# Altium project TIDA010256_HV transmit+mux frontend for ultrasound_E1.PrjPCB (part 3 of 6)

## Sheet 14_XDS110_Debugger.SchDoc
size 431 x 279 mm; Date: Not shown in title block; ApprovedBy: Not shown in title block; CheckedBy: Not shown in title block; Author: Not shown in title block; CompanyName: Not shown in title block; Engineer: Not shown in title block; Organization: Not shown in title block; Address1: Not shown in title block; Address2: Not shown in title block; Address3: Not shown in title block; Address4: Not shown in title block; DocumentNumber: 6; Revision: Use project parameter SCH_Rev; SheetNumber: 6; SheetTotal: 18; PageSetup: Record=PageOptions¦CenterHorizontal=True¦CenterVertical=True¦PrintScale=1.00¦XCorrection=1.00¦YCorrection=1.00¦PrintKind=0¦BorderSize=5000000¦LeftOffset=0¦BottomOffset=0¦Orientation=2¦PaperLength=1000¦PaperWidth=1000¦Scale=100¦PaperSource=15¦PrintQuality=600¦MediaType=1¦DitherType=10¦PaperKind=Letter¦PrintScaleMode=1
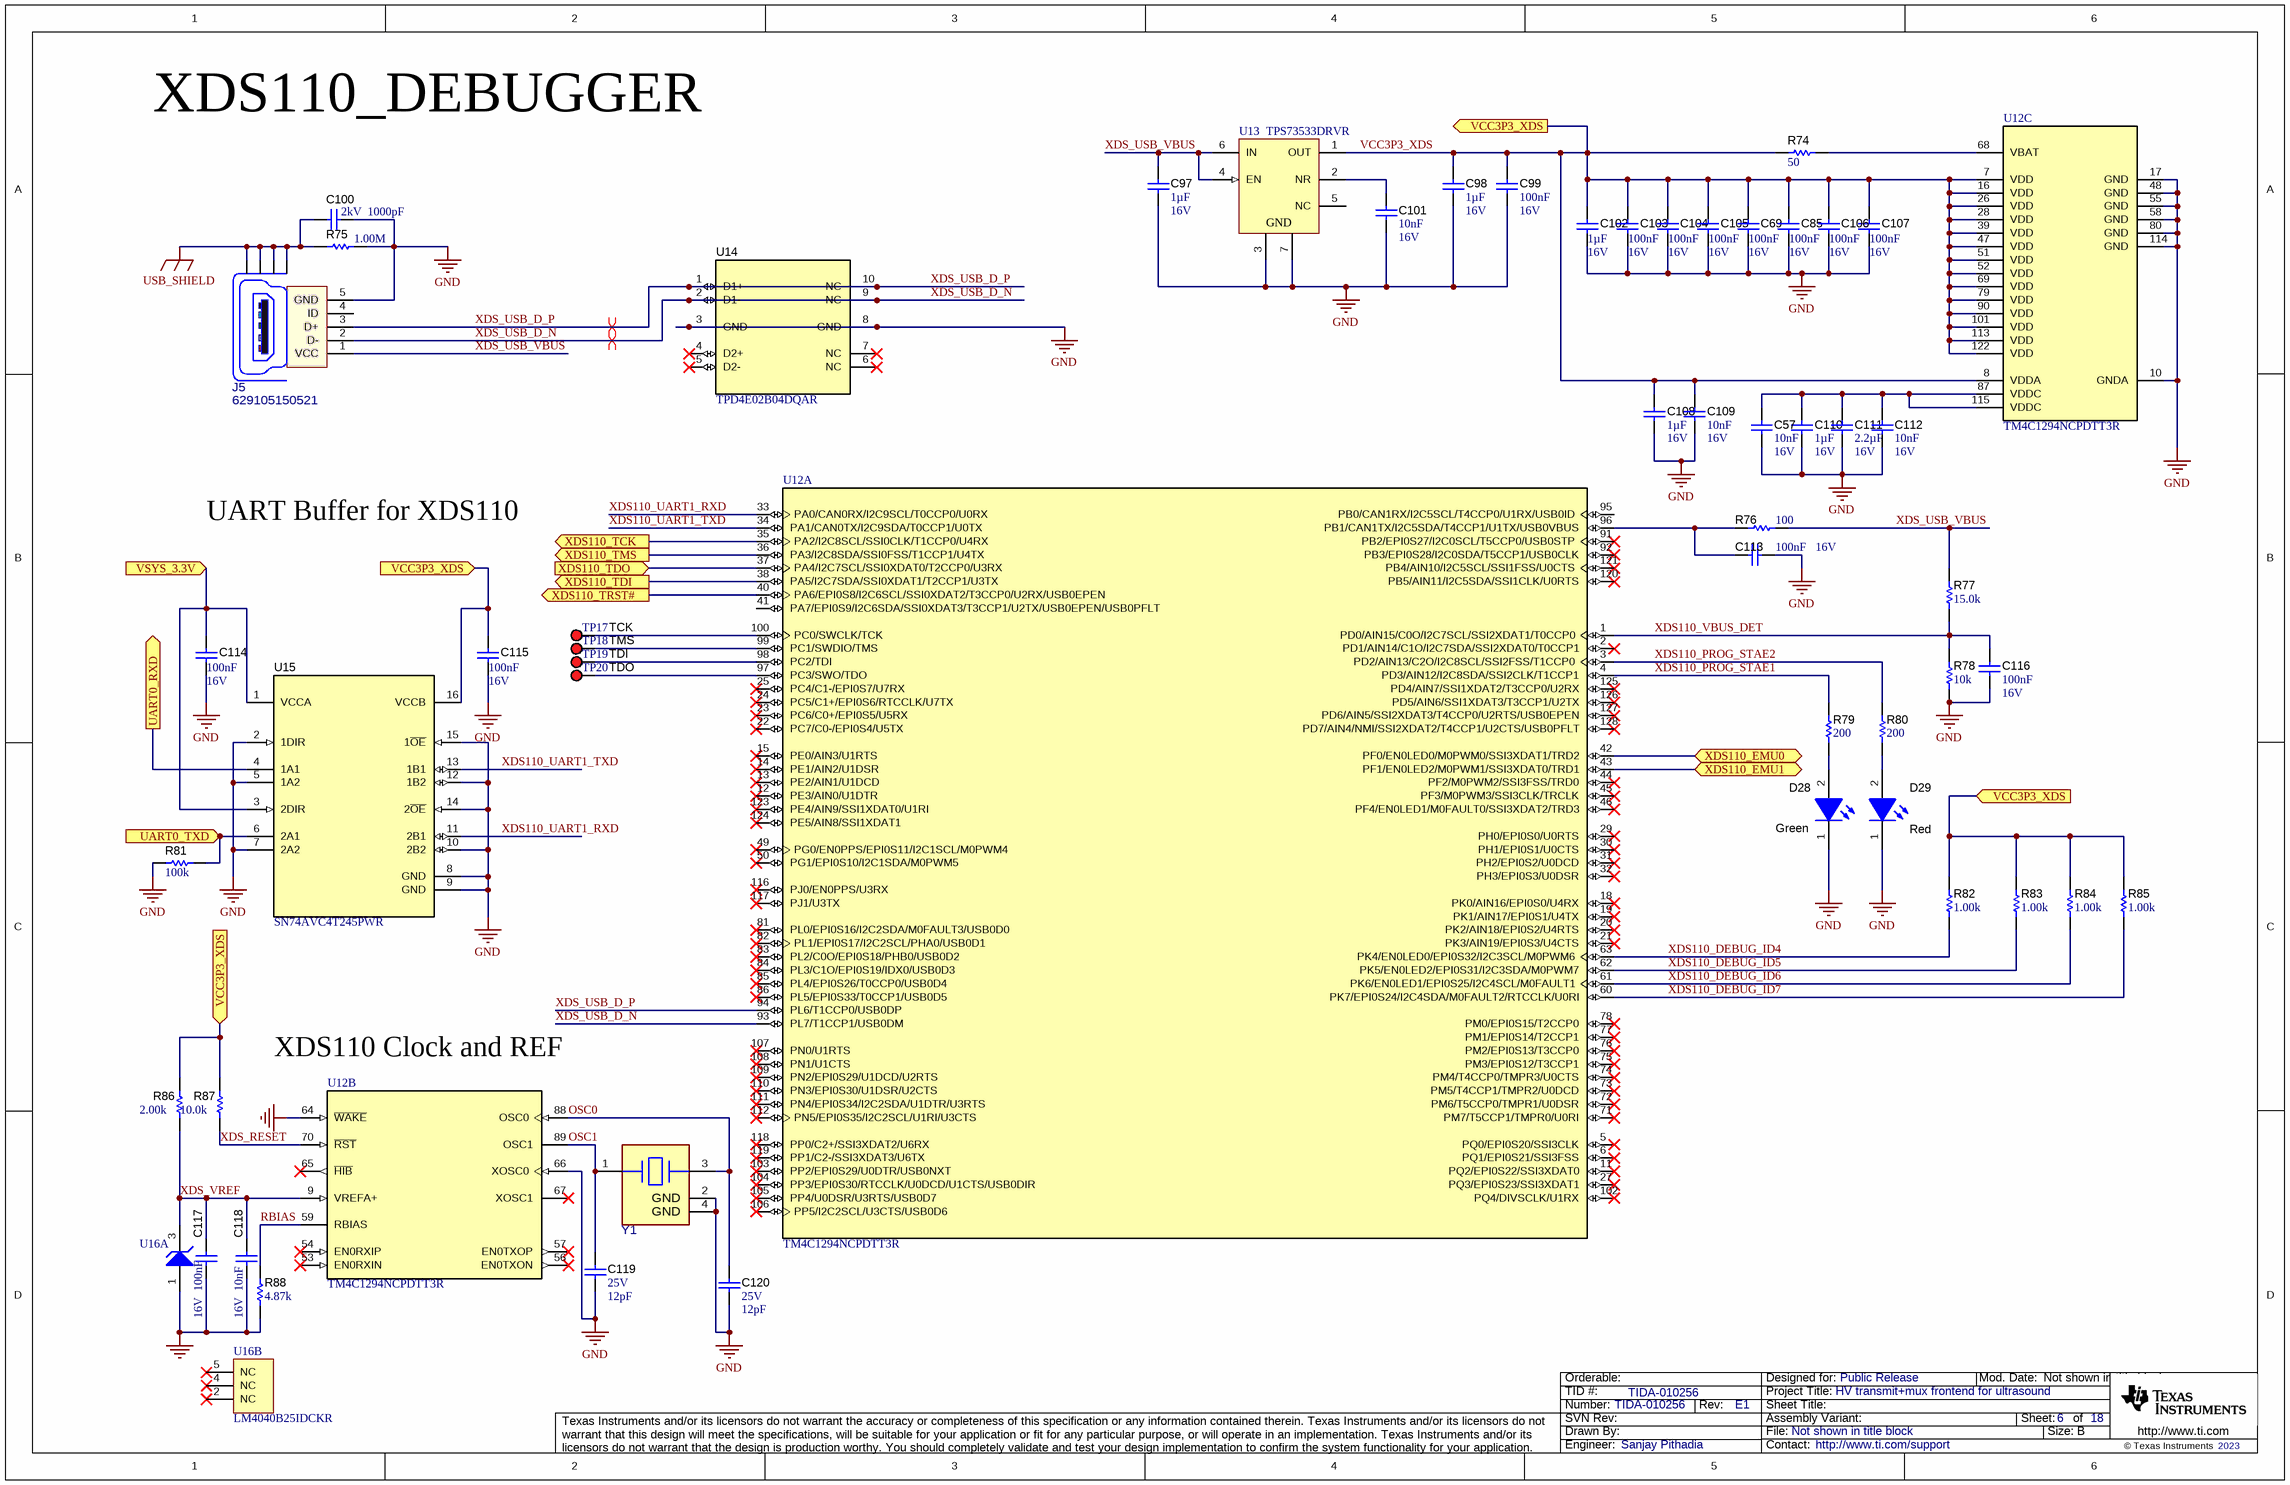
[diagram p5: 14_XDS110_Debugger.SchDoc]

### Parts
C57  Cap_F: 10nF  VDC_V: 16V  [0603]  (hidden comment: C0603C103K4RACTU)
C69  Cap_F: 100nF  VDC_V: 16V  [0603]  (hidden comment: C0603C104M4RACTU)
C85  Cap_F: 100nF  VDC_V: 16V  [0603]  (hidden comment: C0603C104M4RACTU)
C97  Cap_F: 1µF  VDC_V: 16V  [0603]  (hidden comment: C1608X7R1C105K080AC)
C98  Cap_F: 1µF  VDC_V: 16V  [0603]  (hidden comment: C1608X7R1C105K080AC)
C99  Cap_F: 100nF  VDC_V: 16V  [0603]  (hidden comment: C0603C104M4RACTU)
C100  VDC_V: 2kV  ValueDisplayed: 1000pF  [1206_190]  (hidden comment: 202R18W102KV4E)
C101  Cap_F: 10nF  VDC_V: 16V  [0603]  (hidden comment: C0603C103K4RACTU)
C102  Cap_F: 1µF  VDC_V: 16V  [0603]  (hidden comment: C1608X7R1C105K080AC)
C103  Cap_F: 100nF  VDC_V: 16V  [0603]  (hidden comment: C0603C104M4RACTU)
C104  Cap_F: 100nF  VDC_V: 16V  [0603]  (hidden comment: C0603C104M4RACTU)
C105  Cap_F: 100nF  VDC_V: 16V  [0603]  (hidden comment: C0603C104M4RACTU)
C106  Cap_F: 100nF  VDC_V: 16V  [0603]  (hidden comment: C0603C104M4RACTU)
C107  Cap_F: 100nF  VDC_V: 16V  [0603]  (hidden comment: C0603C104M4RACTU)
C108  Cap_F: 1µF  VDC_V: 16V  [0603]  (hidden comment: C1608X7R1C105K080AC)
C109  Cap_F: 10nF  VDC_V: 16V  [0603]  (hidden comment: C0603C103K4RACTU)
C110  Cap_F: 1µF  VDC_V: 16V  [0603]  (hidden comment: C1608X7R1C105K080AC)
C111  Cap_F: 2.2µF  VDC_V: 16V  [0603]  (hidden comment: CC0603KRX7R7BB225)
C112  Cap_F: 10nF  VDC_V: 16V  [0603]  (hidden comment: C0603C103K4RACTU)
C113  Cap_F: 100nF  VDC_V: 16V  [0603]  (hidden comment: C0603C104M4RACTU)
C114  Cap_F: 100nF  VDC_V: 16V  [0603]  (hidden comment: C0603C104M4RACTU)
C115  Cap_F: 100nF  VDC_V: 16V  [0603]  (hidden comment: C0603C104M4RACTU)
C116  Cap_F: 100nF  VDC_V: 16V  [0603]  (hidden comment: C0603C104M4RACTU)
C117  Cap_F: 100nF  VDC_V: 16V  [0603]  (hidden comment: C0603C104M4RACTU)
C118  Cap_F: 10nF  VDC_V: 16V  [0603]  (hidden comment: C0603C103K4RACTU)
C119  VDC_V: 25V  ValueDisplayed: 12pF  [0402]  (hidden comment: GRM1555C1E120JA01D)
C120  VDC_V: 25V  ValueDisplayed: 12pF  [0402]  (hidden comment: GRM1555C1E120JA01D)
D28  value Green  [WL-SMCW_GREEN]  (hidden comment: 150060VS75000)
D29  value Red  [WL-SMCW_RED]  (hidden comment: 150060RS75000)
J5  629105150521  [FP-629105150521_CONN_USB_8MM0_6MM6-MFG]
R74  ValueDisplayed: 50  [0603]  (hidden comment: RCP0603W50R0GEB)
R75  ValueDisplayed: 1.00M  [0603]  (hidden comment: CRCW06031M00FKEA)
R76  ValueDisplayed: 100  [0603]  (hidden comment: CRCW0603100RFKEA)
R77  ValueDisplayed: 15.0k  [0603]  (hidden comment: RC0603FR-0715KL)
R78  ValueDisplayed: 10k  [0603]  (hidden comment: RC0603FR-0715KL)
R79  ValueDisplayed: 200  [0603]  (hidden comment: RC0603FR-07200RL)
R80  ValueDisplayed: 200  [0603]  (hidden comment: RC0603FR-07200RL)
R81  ValueDisplayed: 100k  [0603]  (hidden comment: CRCW0603100KFKEA)
R82  ValueDisplayed: 1.00k  [0603]  (hidden comment: RC0603FR-071KL)
R83  ValueDisplayed: 1.00k  [0603]  (hidden comment: RC0603FR-071KL)
R84  ValueDisplayed: 1.00k  [0603]  (hidden comment: RC0603FR-071KL)
R85  ValueDisplayed: 1.00k  [0603]  (hidden comment: RC0603FR-071KL)
R86  ValueDisplayed: 2.00k  [0603]  (hidden comment: ERJ3EKF2001V)
R87  ValueDisplayed: 10.0k  [0603]  (hidden comment: RMCF0603FT10K0)
R88  ValueDisplayed: 4.87k  [0603]  (hidden comment: RG1608P-4871-B-T5)
TP17  TCK  [Keystone5000]
TP18  TMS  [Keystone5000]
TP19  TDI  [Keystone5000]
TP20  TDO  [Keystone5000]
U12  TM4C1294NCPDTT3R  [PDT0128A]  (parts A,B,C of 3)
U13  TPS73533DRVR  [DRV0006A]
U14  TPD4E02B04DQAR  [DQA0010A]
U15  SN74AVC4T245PWR  [PW0016A_N]
U16  LM4040B25IDCKR  [DCK0005A_N]  (value not drawn)  (parts A,B of 2)
Y1  830064296  [FP-830064296_SMT4_3MM4_2MM7-MFG]  (value not drawn)

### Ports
UART0_RXD (out), UART0_TXD (in), VCC3P3_XDS (in), VCC3P3_XDS (out), VSYS_3.3V (in), XDS110_EMU0 (bidir), XDS110_EMU1 (bidir), XDS110_TCK (out), XDS110_TDI (out), XDS110_TDO (in), XDS110_TMS (out), XDS110_TRST# (out)

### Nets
GND: C57.2 C69.2 C85.2 C97.2 C98.2 C99.2 C100.1 C101.2 C102.2 C103.2 C104.2 C105.2 C106.2 C107.2 C108.2 C109.2 C110.2 C111.2 C112.2 C113.2 C114.2 C115.2 C116.1 C117.2 C118.2 C119.2 C120.2 D28.1(K) D29.1(K) J5.5(GND) R75.2 R78.1 R81.2 R88.1 U12.10(GNDA) U12.17(GND) U12.48(GND) U12.55(GND) U12.58(GND) U12.64(~{WAKE}) U12.66(XOSC0) U12.80(GND) U12.114(GND) U13.3(GND) U13.7(GND) U14.3(GND) U14.8(GND) U15.2(1DIR) U15.5(1A2) U15.7(2A2) U15.8(GND) U15.9(GND) U15.10(2B2) U15.12(1B2) U15.14(2~{OE}) U15.15(1~{OE}) U16.1(ANODE) Y1.2(GND) Y1.4(GND)
USB_SHIELD: C100.2 J5.Z1(Shield) J5.Z2(Shield) J5.Z3(Shield) J5.Z4(Shield) R75.1
OSC0: C120.1 U12.88(OSC0) Y1.3(2_Crystal)
OSC1: C119.1 U12.89(OSC1) Y1.1(1_Crystal)
RBIAS: R88.2 U12.59(RBIAS)
VCC3P3_XDS: C69.1 C85.1 C98.1 C99.1 C102.1 C103.1 C104.1 C105.1 C106.1 C107.1 C108.1 C109.1 C115.1 R74.1 R82.2 R83.2 R84.2 R85.2 R86.2 R87.2 U12.7(VDD) U12.8(VDDA) U12.16(VDD) U12.26(VDD) U12.28(VDD) U12.39(VDD) U12.47(VDD) U12.51(VDD) U12.52(VDD) U12.69(VDD) U12.79(VDD) U12.90(VDD) U12.101(VDD) U12.113(VDD) U12.122(VDD) U13.1(OUT) U15.16(VCCB) ; port VCC3P3_XDS
VSYS_3.3V: C114.1 U15.1(VCCA) U15.3(2DIR) ; port VSYS_3.3V
XDS110_DEBUG_ID4: R82.1 U12.63(PK4/EN0LED0/EPI0S32/I2C3SCL/M0PWM6)
XDS110_DEBUG_ID5: R83.1 U12.62(PK5/EN0LED2/EPI0S31/I2C3SDA/M0PWM7)
XDS110_DEBUG_ID6: R84.1 U12.61(PK6/EN0LED1/EPI0S25/I2C4SCL/M0FAULT1)
XDS110_DEBUG_ID7: R85.1 U12.60(PK7/EPI0S24/I2C4SDA/M0FAULT2/RTCCLK/U0RI)
XDS110_PROG_STAE1: R79.2 U12.4(PD3/AIN12/I2C8SDA/SSI2CLK/T1CCP1)
XDS110_PROG_STAE2: R80.2 U12.3(PD2/AIN13/C2O/I2C8SCL/SSI2FSS/T1CCP0)
XDS110_UART1_RXD: U12.33(PA0/CAN0RX/I2C9SCL/T0CCP0/U0RX) U15.11(2B1)
XDS110_UART1_TXD: U12.34(PA1/CAN0TX/I2C9SDA/T0CCP1/U0TX) U15.13(1B1)
XDS110_VBUS_DET: C116.2 R77.1 R78.2 U12.1(PD0/AIN15/C0O/I2C7SCL/SSI2XDAT1/T0CCP0)
XDS_RESET: R87.1 U12.70(~{RST})
XDS_USB_D_N: J5.2(D-) U12.93(PL7/T1CCP1/USB0DM) U14.2(D1-) U14.9(NC)
XDS_USB_D_P: J5.3(D+) U12.94(PL6/T1CCP0/USB0DP) U14.1(D1+) U14.10(NC)
XDS_USB_VBUS: C97.1 J5.1(VCC) R76.2 R77.2 U13.4(EN) U13.6(IN)
XDS_VREF: C117.1 C118.1 R86.1 U12.9(VREFA+) U16.3(CATHODE)
NetC57_1: C57.1 C110.1 C111.1 C112.1 U12.87(VDDC) U12.115(VDDC)
NetC101_1: C101.1 U13.2(NR)
NetC113_1: C113.1 R76.1 U12.96(PB1/CAN1TX/I2C5SDA/T4CCP1/U1TX/USB0VBUS)
NetD28_2: D28.2(A) R79.1
NetD29_2: D29.2(A) R80.1
NetR74_2: R74.2 U12.68(VBAT)
NetR81_1: R81.1 U15.6(2A1) ; port UART0_TXD
NetTP17_1: TP17.1 U12.100(PC0/SWCLK/TCK)
NetTP18_1: TP18.1 U12.99(PC1/SWDIO/TMS)
NetTP19_1: TP19.1 U12.98(PC2/TDI)
NetTP20_1: TP20.1 U12.97(PC3/SWO/TDO)
NetU12_35: U12.35(PA2/I2C8SCL/SSI0CLK/T1CCP0/U4RX) ; port XDS110_TCK
NetU12_36: U12.36(PA3/I2C8SDA/SSI0FSS/T1CCP1/U4TX) ; port XDS110_TMS
NetU12_37: U12.37(PA4/I2C7SCL/SSI0XDAT0/T2CCP0/U3RX) ; port XDS110_TDO
NetU12_38: U12.38(PA5/I2C7SDA/SSI0XDAT1/T2CCP1/U3TX) ; port XDS110_TDI
NetU12_40: U12.40(PA6/EPI0S8/I2C6SCL/SSI0XDAT2/T3CCP0/U2RX/USB0EPEN) ; port XDS110_TRST#
NetU12_42: U12.42(PF0/EN0LED0/M0PWM0/SSI3XDAT1/TRD2) ; port XDS110_EMU0
NetU12_43: U12.43(PF1/EN0LED2/M0PWM1/SSI3XDAT0/TRD1) ; port XDS110_EMU1
NetU15_4: U15.4(1A1) ; port UART0_RXD

Not connected (* = marked no-connect by the designer): J5 4(ID); U12 2(PD1/AIN14/C1O/I2C7SDA/SSI2XDAT0/T0CCP1)* 5(PQ0/EPI0S20/SSI3CLK)* 6(PQ1/EPI0S21/SSI3FSS)* 11(PQ2/EPI0S22/SSI3XDAT0)* 12(PE3/AIN0/U1DTR)* 13(PE2/AIN1/U1DCD)* 14(PE1/AIN2/U1DSR)* 15(PE0/AIN3/U1RTS)* 18(PK0/AIN16/EPI0S0/U4RX)* 19(PK1/AIN17/EPI0S1/U4TX)* 20(PK2/AIN18/EPI0S2/U4RTS)* 21(PK3/AIN19/EPI0S3/U4CTS)* 22(PC7/C0-/EPI0S4/U5TX)* 23(PC6/C0+/EPI0S5/U5RX)* 24(PC5/C1+/EPI0S6/RTCCLK/U7TX)* 25(PC4/C1-/EPI0S7/U7RX)* 27(PQ3/EPI0S23/SSI3XDAT1)* 29(PH0/EPI0S0/U0RTS)* 30(PH1/EPI0S1/U0CTS)* 31(PH2/EPI0S2/U0DCD)* 32(PH3/EPI0S3/U0DSR)* 41(PA7/EPI0S9/I2C6SDA/SSI0XDAT3/T3CCP1/U2TX/USB0EPEN/USB0PFLT) 44(PF2/M0PWM2/SSI3FSS/TRD0)* 45(PF3/M0PWM3/SSI3CLK/TRCLK)* 46(PF4/EN0LED1/M0FAULT0/SSI3XDAT2/TRD3)* 49(PG0/EN0PPS/EPI0S11/I2C1SCL/M0PWM4)* 50(PG1/EPI0S10/I2C1SDA/M0PWM5)* 53(EN0RXIN)* 54(EN0RXIP)* 56(EN0TXON)* 57(EN0TXOP)* 65(~{HIB})* 67(XOSC1)* 71(PM7/T5CCP1/TMPR0/U0RI)* 72(PM6/T5CCP0/TMPR1/U0DSR)* 73(PM5/T4CCP1/TMPR2/U0DCD)* 74(PM4/T4CCP0/TMPR3/U0CTS)* 75(PM3/EPI0S12/T3CCP1)* 76(PM2/EPI0S13/T3CCP0)* 77(PM1/EPI0S14/T2CCP1)* 78(PM0/EPI0S15/T2CCP0)* 81(PL0/EPI0S16/I2C2SDA/M0FAULT3/USB0D0)* 82(PL1/EPI0S17/I2C2SCL/PHA0/USB0D1)* 83(PL2/C0O/EPI0S18/PHB0/USB0D2)* 84(PL3/C1O/EPI0S19/IDX0/USB0D3)* 85(PL4/EPI0S26/T0CCP0/USB0D4)* 86(PL5/EPI0S33/T0CCP1/USB0D5)* 91(PB2/EPI0S27/I2C0SCL/T5CCP0/USB0STP)* 92(PB3/EPI0S28/I2C0SDA/T5CCP1/USB0CLK)* 95(PB0/CAN1RX/I2C5SCL/T4CCP0/U1RX/USB0ID) 102(PQ4/DIVSCLK/U1RX)* 103(PP2/EPI0S29/U0DTR/USB0NXT)* 104(PP3/EPI0S30/RTCCLK/U0DCD/U1CTS/USB0DIR)* 105(PP4/U0DSR/U3RTS/USB0D7)* 106(PP5/I2C2SCL/U3CTS/USB0D6)* 107(PN0/U1RTS)* 108(PN1/U1CTS)* 109(PN2/EPI0S29/U1DCD/U2RTS)* 110(PN3/EPI0S30/U1DSR/U2CTS)* 111(PN4/EPI0S34/I2C2SDA/U1DTR/U3RTS)* 112(PN5/EPI0S35/I2C2SCL/U1RI/U3CTS)* 116(PJ0/EN0PPS/U3RX)* 117(PJ1/U3TX)* 118(PP0/C2+/SSI3XDAT2/U6RX)* 119(PP1/C2-/SSI3XDAT3/U6TX)* 120(PB5/AIN11/I2C5SDA/SSI1CLK/U0RTS)* 121(PB4/AIN10/I2C5SCL/SSI1FSS/U0CTS)* 123(PE4/AIN9/SSI1XDAT0/U1RI)* 124(PE5/AIN8/SSI1XDAT1)* 125(PD4/AIN7/SSI1XDAT2/T3CCP0/U2RX)* 126(PD5/AIN6/SSI1XDAT3/T3CCP1/U2TX)* 127(PD6/AIN5/SSI2XDAT3/T4CCP0/U2RTS/USB0EPEN)* 128(PD7/AIN4/NMI/SSI2XDAT2/T4CCP1/U2CTS/USB0PFLT)*; U13 5(NC); U14 4(D2+)* 5(D2-)* 6(NC)* 7(NC)*; U16 2(NC)* 4(NC)* 5(NC)*

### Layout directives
differential pair: XDS_USB_D_N, XDS_USB_D_P

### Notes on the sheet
- XDS110_DEBUGGER
- UART Buffer for XDS110
- XDS110 Clock and REF

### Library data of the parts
C57 C101 C109 C112 C118 = CMP-0006853-4: CAP, CERM, 0.01 uF, 16 V, +/- 10%, X7R, 0603; Manufacturer: Kemet; TaMin_C: -55°C; Polarized: N; SizeAreaWB_mm2: 4.68; Value1: Unknown; U/M: EA; Value: 0.01uF; TaMax_C: 125°C; SizeZ_mm: 1; SizeX_mm: 1.6; SizeY_mm: 0.8; SizeArea_mm2: 1.28; AEC Category: Q200
C69 C85 C99 C103-C107 C113-C117 = CMP-0006864-4: CAP, CERM, 0.1 uF, 16 V, +/- 20%, X7R, 0603; Manufacturer: Kemet; TaMin_C: -55°C; Polarized: N; SizeAreaWB_mm2: 4.68; Value1: Unknown; U/M: EA; Value: 0.1uF; TaMax_C: 125°C; SizeZ_mm: 1; SizeX_mm: 1.6; SizeY_mm: 0.8; SizeArea_mm2: 1.28; AEC Category: Q200
C97 C98 C102 C108 C110 = CMP-0007037-4: CAP, CERM, 1 uF, 16 V, +/- 10%, X7R, 0603; Manufacturer: TDK; TaMin_C: -55°C; ESR_ohm: 5.7m; Polarized: N; SizeAreaWB_mm2: 4.68; Value1: 0.0057 ohm; U/M: EA; Value: 1uF; TaMax_C: 125°C; SizeZ_mm: 1; SizeX_mm: 1.6; SizeY_mm: 0.8; SizeArea_mm2: 1.28; AEC Category: Q200
C100 = CMP-0008572-2: CAP, CERM, 1000 pF, 2000 V, +/- 10%, X7R, 1206_190; Manufacturer: Johanson Technology; TaMin_C: -55°C; Polarized: N; SizeAreaWB_mm2: 10.92; Value1: Unknown; U/M: EA; Value: 1000pF; TaMax_C: 125°C; SizeZ_mm: 1.9; SizeX_mm: 3.2; SizeY_mm: 1.6; Cap_Case: 1206; Value2: 2000V; SizeArea_mm2: 5.12; Cap_F: 1nF; AEC Category: Q200
C111 = CMP-0079605-1: CAP, CERM, 2.2 µF, 16 V,+/- 10%, X7R, 0603; Manufacturer: Yageo America; TaMin_C: -55°C; Polarized: N; SizeAreaWB_mm2: 4.68; U/M: EA; Value: 2.2uF; TaMax_C: 125°C; SizeZ_mm: 1; SizeX_mm: 1.6; SizeY_mm: 0.8; SizeArea_mm2: 1.28; AEC Category: Q200
C119 C120 = CMP-0006375-2: CAP, CERM, 12 pF, 25 V, +/- 5%, C0G/NP0, 0402; Manufacturer: MuRata; TaMin_C: -55°C; Polarized: N; SizeAreaWB_mm2: 3; Value1: Unknown; U/M: EA; Value: 12pF; TaMax_C: 125°C; SizeZ_mm: 0.6; SizeX_mm: 1; SizeY_mm: 0.5; AEC Category: Q200
D28 = CMP-0002894-2: LED, Green, SMD; Manufacturer: Wurth Elektronik; Type: AlInGaP; Value2: 2V; Io_A: 20mA; Value1: W
D29 = CMP-0002947-3: LED, Red, SMD; Manufacturer: Wurth Elektronik; Value1: 0.072W; Vf_V: 2V; Angle: 140; Tjmax_C: 85°C; Type: AlInGaP; Vr_V: 5V; Io_A: 30mA; Power_TotalModule: 72mW
J5 = CMP-0086695-3: USB - micro B USB 2.0 Receptacle Connector 5 Position Surface Mount, Right Angle; Through Hole; Manufacturer: Wurth Electronics; Shrouded: true; Voltage_V: 30V; Current_A: 3A; ContactFinish: Gold
R74 = CMP-0082504-1: RES, 50, 2%, 3.9 W, 0603; Manufacturer: Vishay-Dale; Value_Code: 50R0; SizeAreaWB_mm2: 4.68; SizeArea_mm2: 1.28; AEC Qualified: N; AEC Category: Q200; Value: 50; SizeZ_mm: 1; TempCo: 150 ppm/C; Power_W: 3.9W; SizeY_mm: 0.8; SizeX_mm: 1.6
R75 = CMP-0022138-4: RES, 1.00 M, 1%, 0.1 W, AEC-Q200 Grade 0, 0603; Manufacturer: Vishay-Dale; Power_W: 100mW; TempCo: 100 ppm/C; Value_Code: 1M00; Value: 1.00Meg; EIA_Code: E96; Res_ohm: 1M; SizeX_mm: 1.6; SizeY_mm: 0.8; SizeZ_mm: 1; Value2: 0.1W; SizeArea_mm2: 1.28; AEC Qualified: Y; VDC_V: 75V; AEC Category: Q200; AEC Grade: 0
R76 = CMP-0021991-4: RES, 100, 1%, 0.1 W, AEC-Q200 Grade 0, 0603; Manufacturer: Vishay-Dale; Power_W: 100mW; TempCo: 100 ppm/C; Value_Code: 100R; Value: 100; EIA_Code: E96; SizeX_mm: 1.6; SizeY_mm: 0.8; SizeZ_mm: 1; Value2: 0.1W; SizeArea_mm2: 1.28; AEC Qualified: Y; VDC_V: 75V; AEC Category: Q200; AEC Grade: 0
R77 = CMP-0022816-5: RES, 15.0 k, 1%, 0.1 W, 0603; Manufacturer: Yageo; Power_W: 100mW; TempCo: 100 ppm/C; Value_Code: 15k0; Value: 15.0k; EIA_Code: E96; Res_ohm: 15k; SizeX_mm: 1.6; SizeY_mm: 0.8; SizeZ_mm: 1; Value2: 0.1W; SizeArea_mm2: 1.28; AEC Qualified: N; VDC_V: 75V; AEC Category: Q200; SizeAreaWB_mm2: 4.68
R78 = CMP-0022816-5: RES, 10k, 1%, 0.1 W, 0603; Manufacturer: Yageo; Power_W: 100mW; TempCo: 100 ppm/C; Value_Code: 15k0; Value: 15.0k; EIA_Code: E96; Res_ohm: 15k; SizeX_mm: 1.6; SizeY_mm: 0.8; SizeZ_mm: 1; Value2: 0.1W; SizeArea_mm2: 1.28; AEC Qualified: N; VDC_V: 75V; AEC Category: Q200; SizeAreaWB_mm2: 4.68
R79 R80 = CMP-0022902-5: RES, 200, 1%, 0.1 W, 0603; Manufacturer: Yageo; Power_W: 100mW; TempCo: 100 ppm/C; Value_Code: 200R; Value: 200; EIA_Code: E96; SizeX_mm: 1.6; SizeY_mm: 0.8; SizeZ_mm: 1; Value2: 0.1W; SizeArea_mm2: 1.28; AEC Qualified: N; VDC_V: 75V; AEC Category: Q200; SizeAreaWB_mm2: 4.68
R81 = CMP-0021990-4: RES, 100 k, 1%, 0.1 W, AEC-Q200 Grade 0, 0603; Manufacturer: Vishay-Dale; Power_W: 100mW; TempCo: 100 ppm/C; Value: 100k; EIA_Code: E96; SizeX_mm: 1.6; SizeY_mm: 0.8; SizeZ_mm: 1; Value2: 0.1W; SizeArea_mm2: 1.28; AEC Qualified: Y; VDC_V: 75V; AEC Category: Q200; AEC Grade: 0
R82-R85 = CMP-0022895-5: RES, 1.00 k, 1%, 0.1 W, 0603; Manufacturer: Yageo; Power_W: 100mW; TempCo: 100 ppm/C; Value_Code: 1k00; Value: 1.00k; EIA_Code: E96; Res_ohm: 1k; SizeX_mm: 1.6; SizeY_mm: 0.8; SizeZ_mm: 1; Value2: 0.1W; SizeArea_mm2: 1.28; AEC Qualified: N; VDC_V: 75V; AEC Category: Q200; SizeAreaWB_mm2: 4.68
R86 = CMP-0078663-1: RES, 2.00 k, 1%, 0.1 W, AEC-Q200 Grade 0, 0603; Manufacturer: Panasonic; Power_W: 100mW; TempCo: 100 ppm/C; Value_Code: 2k00; Value: 2.00k; EIA_Code: E96; Res_ohm: 2k; SizeX_mm: 1.6; SizeY_mm: 0.8; SizeZ_mm: 1; Value2: 0.1W; SizeArea_mm2: 1.28; AEC Qualified: Y; AEC Grade: 0; AEC Category: Q200
R87 = CMP-0023341-3: RES, 10.0 k, 1%, 0.1 W, AEC-Q200 Grade 0, 0603; Manufacturer: Stackpole Electronics Inc; Power_W: 100mW; TempCo: 100 ppm/C; Value_Code: 10k0; U/M: EA; Value: 10.0k; EIA_Code: E96; Res_ohm: 10k; SizeX_mm: 1.6; SizeY_mm: 0.8; SizeZ_mm: 1; Value2: 0.1W; SizeArea_mm2: 1.28; AEC Qualified: Y; VDC_V: 75V; AEC Grade: 0; AEC Category: Q200
R88 = CMP-0023560-3: RES, 4.87 k, 0.1%, 0.1 W, 0603; Manufacturer: Susumu Co Ltd; Power_W: 100mW; TempCo: 25 ppm/C; Value_Code: 4k87; U/M: EA; Value: 4.87k; EIA_Code: E192; SizeX_mm: 1.6; SizeY_mm: 0.8; SizeZ_mm: 1; Value2: 0.1W; SizeArea_mm2: 1.28; VDC_V: 75V; AEC Category: Q200
TP17-TP20 = CMP-0055137-2: Test Point, Miniature, Red, TH; Manufacturer: Keystone Electronics; ContactFinish: Silver; CNHeader: FALSE; CT: TRUE; Green_Lifecycle: Active; Green_REACh: Passed
U12 = CMP-0029865-2: Tiva C Series Microcontroller, 1024 KB Flash, 256 KB SRAM, 12 Bit, 20 Channels, -40 to 105 degC, 128-Pin TQFP (PDT), Green (RoHS & no Sb/Br), Tape and Reel; Manufacturer: Texas Instruments; ADC Channels: 20; CPU: ARM Cortex-M4; Flash: 1024 KB; ADC Resolution: 12 Bits; Max Speed: 120 MHz; SRAM: 256 KB; SizeAreaWB_mm2: 324.0; SizeArea_mm2: 256.0; SizeX_mm: 16.0; SizeZ_mm: 1.2; CompType: IC
U13 = CMP-0036330-5: Single Output High PSRR LDO, 500 mA, Fixed 3.3 V Output, 2.7 to 6.5 V Input, with Low IQ, 6-pin SON (DRV), -40 to 125 degC, Green (RoHS & no Sb/Br); Manufacturer: Texas Instruments; SubFamily: Single Channel LDO; Vin(Max)(V): 6.5; Vin(Min)(V): 2.7; Iout(Max)(A): 0.5; Iq(Typ)(mA): 0.04; Fixed Output Options(V): 3.3; Vdo(Typ)(mV): 280; Accuracy(%): 2; CompType: IC; SizeAreaWB_mm2: 9; SizeArea_mm2: 4; SizeZ_mm: 0.8
U14 = CMP-0073612-3: 4-Channel ESD Protection Diode for USB Type-C and HDMI 2.0, DQA0010A (USON-10); Alternate Manufacturer: Texas Instruments; Green_Lifecycle: Active; SizeAreaWB_mm2: 7.0; Green_REACh: Passed; SizeZ_mm: 0.55; SizeX_mm: 1.0; SizeY_mm: 2.5; CompType: IC; AEC Category: Q200; AEC Qualified: Y
U15 = CMP-0066448-2: 4-Bit Dual-Supply Bus Transceiver with Configurable Voltage-Level Shifting and 3-State Outputs, PW0016A (TSSOP-16); Alternate Manufacturer: Texas Instruments; Green_Lifecycle: Active; SizeAreaWB_mm2: 58.8; Green_REACh: Passed; SizeZ_mm: 1.2; SizeX_mm: 6.4; SizeY_mm: 5.0; SizeArea_mm2: 32.0; CompType: IC; AEC Category: Q200; AEC Qualified: N
U16 = CMP-0032785-2: Precision Micropower Shunt Voltage Reference, 0.2% accuracy, 2.5 V, 15 ppm / degC, 15 mA, -40 to 85 degC, 5-pin SC70 (DCK), Green (RoHS & no Sb/Br); Manufacturer: Texas Instruments; Iout/Iz(Max)(mA): 15; Temp Coeff(Max)(ppm/ degree C): 100; VO(V): 2.5; Min Iz for Regulation(uA): 75; Initial Accuracy @ 25/deg C(%): 0.2; Rating: Catalog; AEC Category: Q200; AEC Qualified: N; CompType: IC; SizeAreaWB_mm2: 9.3; SizeArea_mm2: 4.2; SizeX_mm: 2.1; SizeY_mm: 2.0; SizeZ_mm: 1.1
Y1 = CMP-0094478-1: Crystal 16 MHz ±20ppm Crystal 8pF 70 Ohms 4-SMD, No Lead; Manufacturer: Wurth; SizeZ_mm: 0.8mm; Frequency_Fixed: 16MHz; Esr: 70

## Sheet 15_AM243x_BootMode.SchDoc
size 431 x 279 mm; Date: Not shown in title block; ApprovedBy: Not shown in title block; CheckedBy: Not shown in title block; Author: Not shown in title block; CompanyName: Not shown in title block; Engineer: Not shown in title block; Organization: Not shown in title block; Address1: Not shown in title block; Address2: Not shown in title block; Address3: Not shown in title block; Address4: Not shown in title block; DocumentNumber: 7; Revision: Use project parameter SCH_Rev; SheetNumber: 7; SheetTotal: 18; PageSetup: Record=PageOptions¦CenterHorizontal=True¦CenterVertical=True¦PrintScale=1.00¦XCorrection=1.00¦YCorrection=1.00¦PrintKind=0¦BorderSize=5000000¦LeftOffset=0¦BottomOffset=0¦Orientation=2¦PaperLength=1000¦PaperWidth=1000¦Scale=100¦PaperSource=15¦PrintQuality=600¦MediaType=1¦DitherType=10¦PaperKind=Letter¦PrintScaleMode=1
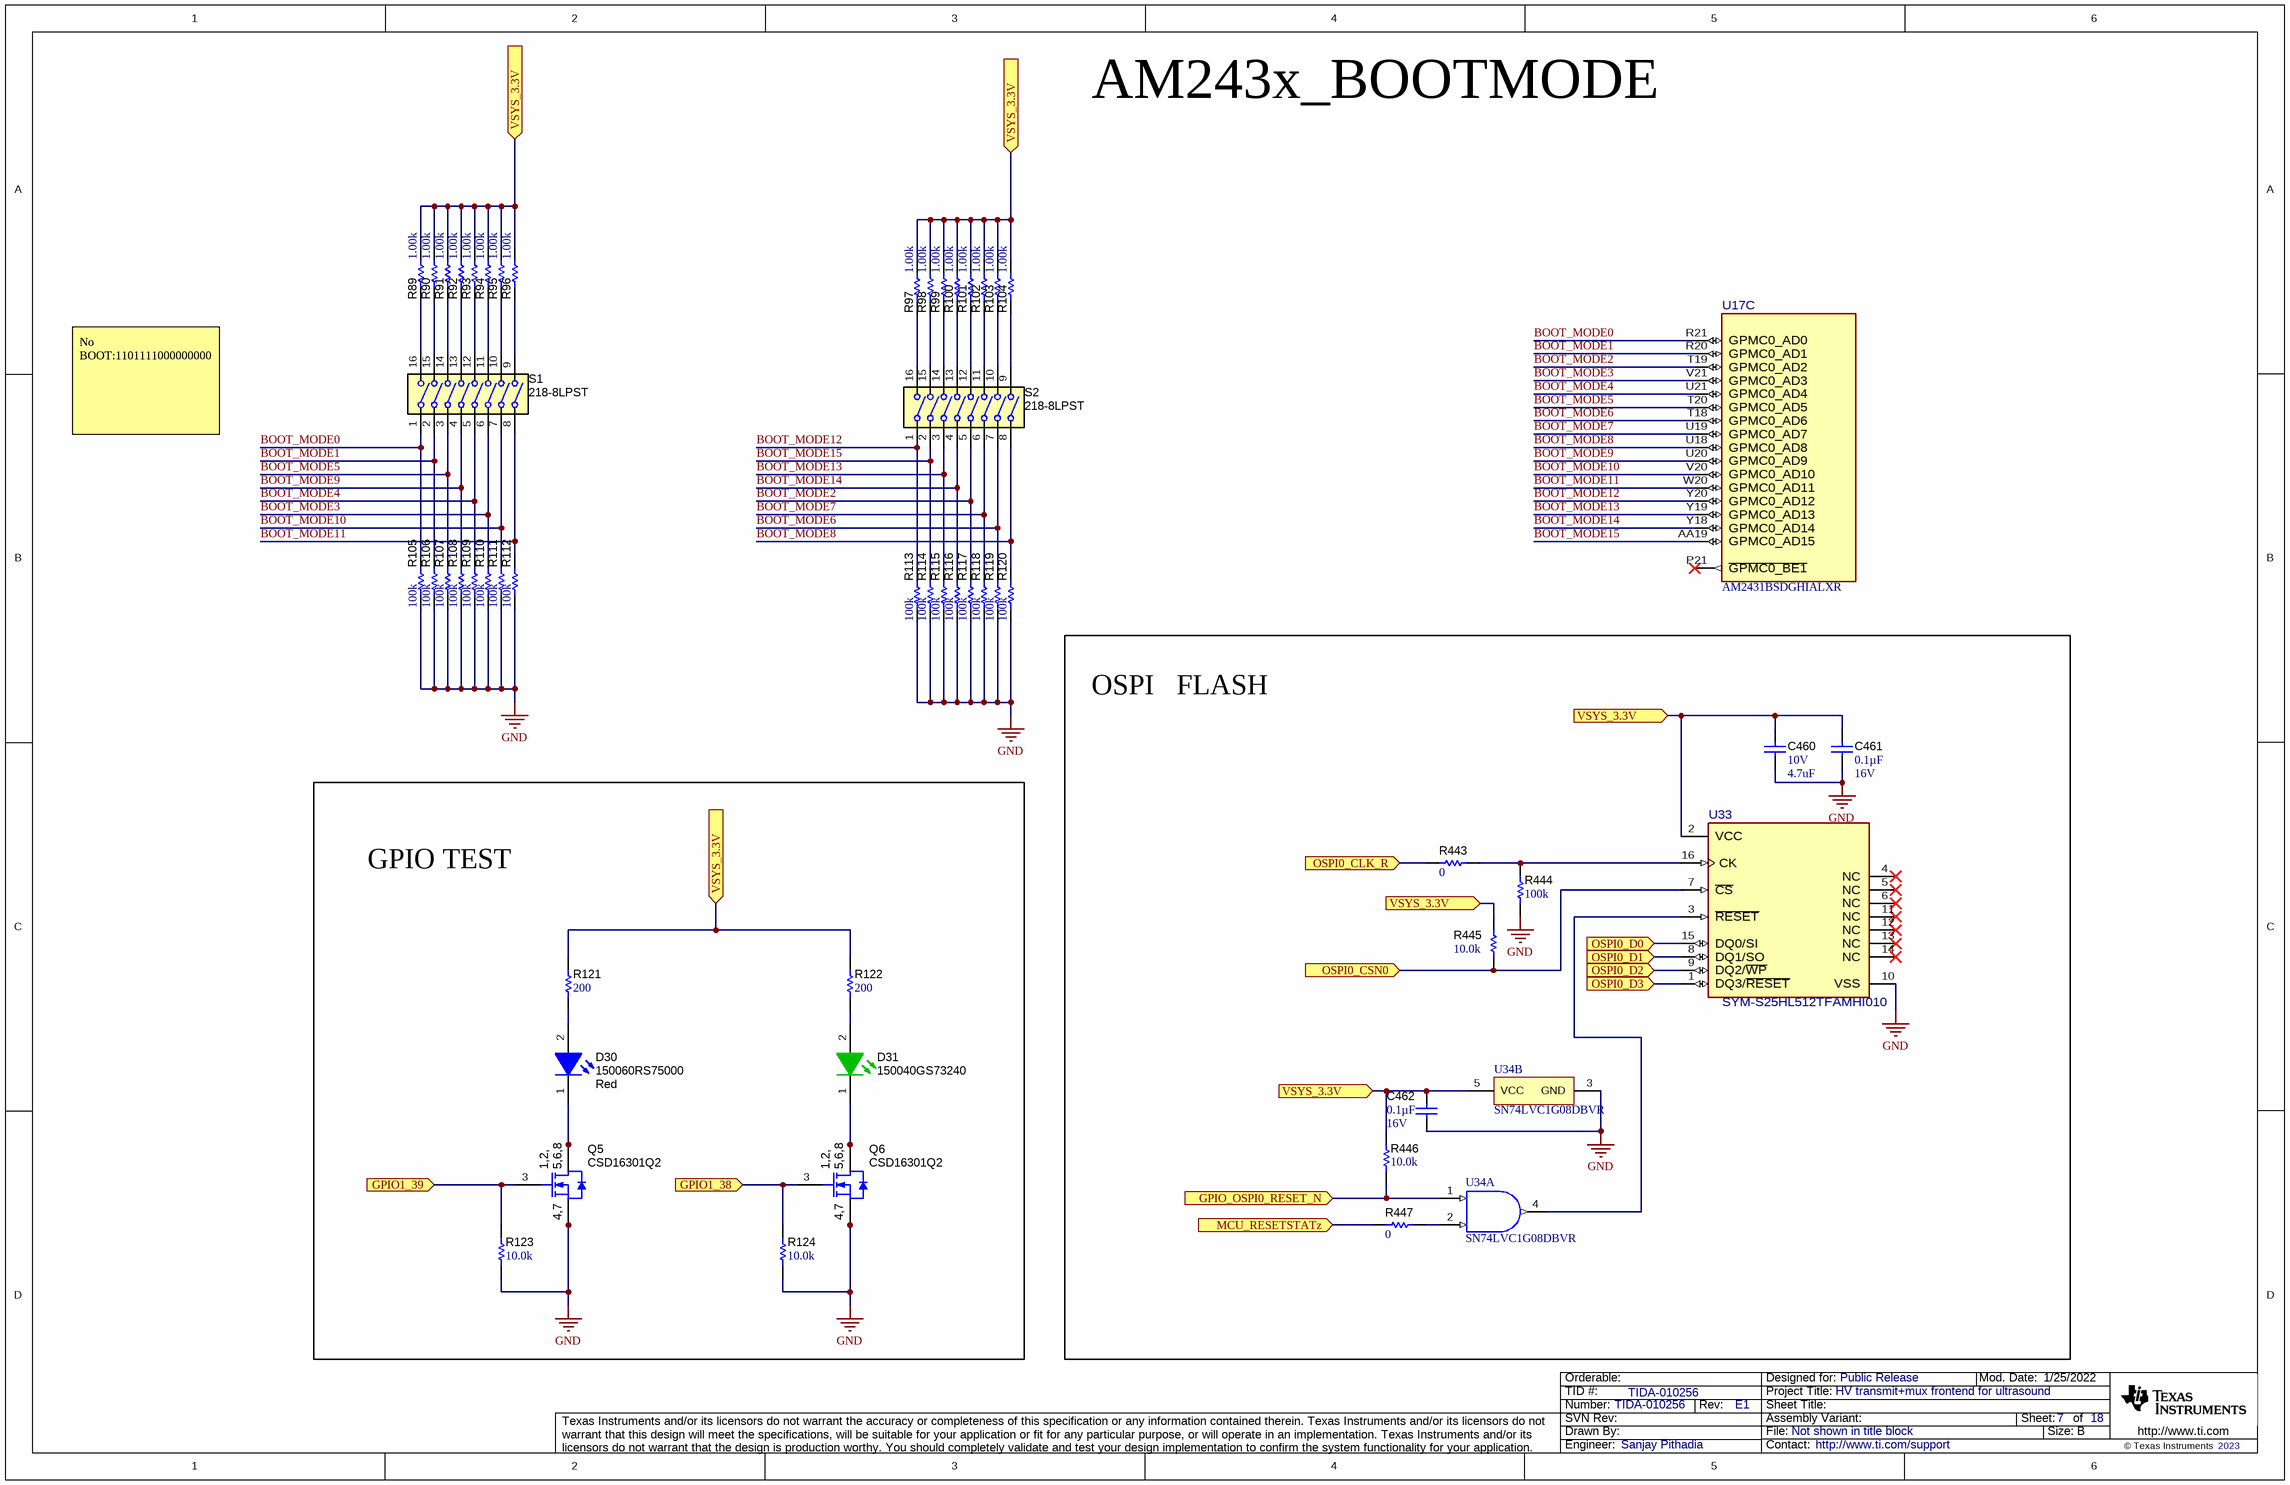
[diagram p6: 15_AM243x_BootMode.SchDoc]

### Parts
C460  VDC_V: 10V  ValueDisplayed: 4.7uF  [0402]  (hidden comment: GRM155R61A475MEAAD)
C461  ValueDisplayed: 0.1µF  VDC_V: 16V  [0201_033]  (hidden comment: GRM033R61C104KE14D)
C462  ValueDisplayed: 0.1µF  VDC_V: 16V  [0201_033]  (hidden comment: GRM033R61C104KE14D)
D30  150060RS75000  value Red  [WL-SMCW_RED]
D31  150040GS73240  [WL-SMCC_0402_Green]
Q5  CSD16301Q2  [DQK0006C]
Q6  CSD16301Q2  [DQK0006C]
R89  ValueDisplayed: 1.00k  [0603]  (hidden comment: CRCW06031K00FKEA)
R90  ValueDisplayed: 1.00k  [0603]  (hidden comment: CRCW06031K00FKEA)
R91  ValueDisplayed: 1.00k  [0603]  (hidden comment: CRCW06031K00FKEA)
R92  ValueDisplayed: 1.00k  [0603]  (hidden comment: CRCW06031K00FKEA)
R93  ValueDisplayed: 1.00k  [0603]  (hidden comment: CRCW06031K00FKEA)
R94  ValueDisplayed: 1.00k  [0603]  (hidden comment: CRCW06031K00FKEA)
R95  ValueDisplayed: 1.00k  [0603]  (hidden comment: CRCW06031K00FKEA)
R96  ValueDisplayed: 1.00k  [0603]  (hidden comment: CRCW06031K00FKEA)
R97  ValueDisplayed: 1.00k  [0603]  (hidden comment: CRCW06031K00FKEA)
R98  ValueDisplayed: 1.00k  [0603]  (hidden comment: CRCW06031K00FKEA)
R99  ValueDisplayed: 1.00k  [0603]  (hidden comment: CRCW06031K00FKEA)
R100  ValueDisplayed: 1.00k  [0603]  (hidden comment: CRCW06031K00FKEA)
R101  ValueDisplayed: 1.00k  [0603]  (hidden comment: CRCW06031K00FKEA)
R102  ValueDisplayed: 1.00k  [0603]  (hidden comment: CRCW06031K00FKEA)
R103  ValueDisplayed: 1.00k  [0603]  (hidden comment: CRCW06031K00FKEA)
R104  ValueDisplayed: 1.00k  [0603]  (hidden comment: CRCW06031K00FKEA)
R105  ValueDisplayed: 100k  [0603]  (hidden comment: CRCW0603100KFKEA)
R106  ValueDisplayed: 100k  [0603]  (hidden comment: CRCW0603100KFKEA)
R107  ValueDisplayed: 100k  [0603]  (hidden comment: CRCW0603100KFKEA)
R108  ValueDisplayed: 100k  [0603]  (hidden comment: CRCW0603100KFKEA)
R109  ValueDisplayed: 100k  [0603]  (hidden comment: CRCW0603100KFKEA)
R110  ValueDisplayed: 100k  [0603]  (hidden comment: CRCW0603100KFKEA)
R111  ValueDisplayed: 100k  [0603]  (hidden comment: CRCW0603100KFKEA)
R112  ValueDisplayed: 100k  [0603]  (hidden comment: CRCW0603100KFKEA)
R113  ValueDisplayed: 100k  [0603]  (hidden comment: CRCW0603100KFKEA)
R114  ValueDisplayed: 100k  [0603]  (hidden comment: CRCW0603100KFKEA)
R115  ValueDisplayed: 100k  [0603]  (hidden comment: CRCW0603100KFKEA)
R116  ValueDisplayed: 100k  [0603]  (hidden comment: CRCW0603100KFKEA)
R117  ValueDisplayed: 100k  [0603]  (hidden comment: CRCW0603100KFKEA)
R118  ValueDisplayed: 100k  [0603]  (hidden comment: CRCW0603100KFKEA)
R119  ValueDisplayed: 100k  [0603]  (hidden comment: CRCW0603100KFKEA)
R120  ValueDisplayed: 100k  [0603]  (hidden comment: CRCW0603100KFKEA)
R121  ValueDisplayed: 200  [0603]  (hidden comment: RC0603FR-07200RL)
R122  ValueDisplayed: 200  [0603]  (hidden comment: RC0603FR-07200RL)
R123  ValueDisplayed: 10.0k  [0603]  (hidden comment: RMCF0603FT10K0)
R124  ValueDisplayed: 10.0k  [0603]  (hidden comment: RMCF0603FT10K0)
R443  ValueDisplayed: 0  [0603]  (hidden comment: ERJ-3GEY0R00V)
R444  ValueDisplayed: 100k  [0603]  (hidden comment: CRCW0603100KFKEA)
R445  ValueDisplayed: 10.0k  [ERA3A]  (hidden comment: ERA3ARB103V)
R446  ValueDisplayed: 10.0k  [ERA3A]  (hidden comment: ERA3ARB103V)
R447  ValueDisplayed: 0  [0603]  (hidden comment: ERJ-3GEY0R00V)
S1  218-8LPST  [SW_218-8LP]
S2  218-8LPST  [SW_218-8LP]
U17  AM2431BSDGHIALXR  [ALX0293A-MFG]  (part C of 9)
U33  SYM-S25HL512TFAMHI010  [FP-S25HL512TFAMHI010_SO16-MFG]
U34  SN74LVC1G08DBVR  [DBV0005A_N]  (parts A,B of 2)

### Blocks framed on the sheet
OSPI   FLASH: C460-C462 R443-R447 U33 U34
GPIO TEST: D30 D31 Q5 Q6 R121-R124

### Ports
GPIO1_38 (in), GPIO1_39 (in), GPIO_OSPI0_RESET_N (in), MCU_RESETSTATz (in), OSPI0_CLK_R (in), OSPI0_CSN0 (in), OSPI0_D0 (in), OSPI0_D1 (in), OSPI0_D2 (in), OSPI0_D3 (in), VSYS_3.3V (in)

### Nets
GND: C460.2 C461.2 C462.2 Q5.4(S) Q5.7(S) Q6.4(S) Q6.7(S) R105.1 R106.1 R107.1 R108.1 R109.1 R110.1 R111.1 R112.1 R113.1 R114.1 R115.1 R116.1 R117.1 R118.1 R119.1 R120.1 R123.1 R124.1 R444.1 U33.10(VSS) U34.3(GND)
BOOT_MODE0: R105.2 S1.1 U17.R21(GPMC0_AD0)
BOOT_MODE1: R106.2 S1.2 U17.R20(GPMC0_AD1)
BOOT_MODE2: R117.2 S2.5 U17.T19(GPMC0_AD2)
BOOT_MODE3: R110.2 S1.6 U17.V21(GPMC0_AD3)
BOOT_MODE4: R109.2 S1.5 U17.U21(GPMC0_AD4)
BOOT_MODE5: R107.2 S1.3 U17.T20(GPMC0_AD5)
BOOT_MODE6: R119.2 S2.7 U17.T18(GPMC0_AD6)
BOOT_MODE7: R118.2 S2.6 U17.U19(GPMC0_AD7)
BOOT_MODE8: R120.2 S2.8 U17.U18(GPMC0_AD8)
BOOT_MODE9: R108.2 S1.4 U17.U20(GPMC0_AD9)
BOOT_MODE10: R111.2 S1.7 U17.V20(GPMC0_AD10)
BOOT_MODE11: R112.2 S1.8 U17.W20(GPMC0_AD11)
BOOT_MODE12: R113.2 S2.1 U17.Y20(GPMC0_AD12)
BOOT_MODE13: R115.2 S2.3 U17.Y19(GPMC0_AD13)
BOOT_MODE14: R116.2 S2.4 U17.Y18(GPMC0_AD14)
BOOT_MODE15: R114.2 S2.2 U17.AA19(GPMC0_AD15)
VSYS_3.3V: C460.1 C461.1 C462.1 R89.2 R90.2 R91.2 R92.2 R93.2 R94.2 R95.2 R96.2 R97.2 R98.2 R99.2 R100.2 R101.2 R102.2 R103.2 R104.2 R121.2 R122.2 R445.2 R446.2 U33.2(VCC) U34.5(VCC) ; port VSYS_3.3V
NetD30_1: D30.1(K) Q5.1(D) Q5.2(D) Q5.5(D) Q5.6(D) Q5.8(D)
NetD30_2: D30.2(A) R121.1
NetD31_1: D31.1(K) Q6.1(D) Q6.2(D) Q6.5(D) Q6.6(D) Q6.8(D)
NetD31_2: D31.2(A) R122.1
NetQ5_3: Q5.3(G) R123.2 ; port GPIO1_39
NetQ6_3: Q6.3(G) R124.2 ; port GPIO1_38
NetR89_1: R89.1 S1.16(1A)
NetR90_1: R90.1 S1.15(2A)
NetR91_1: R91.1 S1.14(3A)
NetR92_1: R92.1 S1.13(4A)
NetR93_1: R93.1 S1.12(5A)
NetR94_1: R94.1 S1.11(6A)
NetR95_1: R95.1 S1.10(7A)
NetR96_1: R96.1 S1.9(8A)
NetR97_1: R97.1 S2.16(1A)
NetR98_1: R98.1 S2.15(2A)
NetR99_1: R99.1 S2.14(3A)
NetR100_1: R100.1 S2.13(4A)
NetR101_1: R101.1 S2.12(5A)
NetR102_1: R102.1 S2.11(6A)
NetR103_1: R103.1 S2.10(7A)
NetR104_1: R104.1 S2.9(8A)
NetR443_1: R443.1 ; port OSPI0_CLK_R
NetR443_2: R443.2 R444.2 U33.16(CK)
NetR445_1: R445.1 U33.7(~{CS}) ; port OSPI0_CSN0
NetR446_1: R446.1 U34.1(A) ; port GPIO_OSPI0_RESET_N
NetR447_1: R447.1 ; port MCU_RESETSTATz
NetR447_2: R447.2 U34.2(B)
NetU17_L19: U33.15(DQ0/SI) ; port OSPI0_D0
NetU17_L21: U33.9(DQ2/~{WP}) ; port OSPI0_D2
NetU17_N19: U33.1(DQ3/~{RESET}) ; port OSPI0_D3
NetU17_N20: U33.8(DQ1/SO) ; port OSPI0_D1
NetU33_3: U33.3(~{RESET}) U34.4(Y)

Not connected (* = marked no-connect by the designer): U17 P21(~{GPMC0_BE1})*; U33 4(NC)* 5(NC)* 6(NC)* 11(NC)* 12(NC)* 13(NC)* 14(NC)*

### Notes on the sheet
- AM243x_BOOTMODE
- No BOOT:1101111000000000

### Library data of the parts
C460 = CMP-0006582-2: CAP, CERM, 4.7 uF, 10 V, +/- 20%, X5R, 0402; Manufacturer: MuRata; TaMin_C: -55°C; Polarized: N; SizeAreaWB_mm2: 3; Value1: Unknown; U/M: EA; Value: 4.7uF; TaMax_C: 85°C; SizeZ_mm: 0.6; SizeX_mm: 1; SizeY_mm: 0.5; Cap_F: 4.7µF; AEC Category: Q200
C461 C462 = CMP-0086192-1: CAP, CERM, 0.1 µF, 16 V,+/- 10%, X5R, 0201; Manufacturer: MuRata; TaMax_C: 85°C; AEC Category: Q200; U/M: EA; SizeZ_mm: 0.33; SizeArea_mm2: 0.18; Polarized: N; SizeAreaWB_mm2: 2.08; Cap_F: 100nF; Cap_Case: 0201; SizeY_mm: 0.3; SizeX_mm: 0.6; Value: 0.1uF; TaMin_C: -55°C
D30 = CMP-0002947-3: as D29 on sheet 14_XDS110_Debugger
D31 = CMP-0081765-2: LED, Green, SMD; Manufacturer: Wurth Elektronik; Vr_V: 5V; Io_A: 20mA; Tjmax_C: 95°C; Ir_A: 10µA; Power_TotalModule: 99mW; Value2: 3.2V; SizeArea_mm2: 0.5; SizeX_mm: 1; Value1: 0.099W; Angle: 120; Type: InGaN; SizeAreaWB_mm2: 3
Q5 Q6 = CMP-0000248-1: MOSFET, N-CH, 25 V, 5 A, DQK0006C (WSON-6); Alternate Manufacturer: None; Manufacturer: Texas Instruments; SizeZ_mm: 0.8; ChType: N; Value2: 2 nC; Value1: 0.02; VdsMax_V: 25V; SizeX_mm: 2; Vgs_V: 10V; Value: 25V; Rdson45_ohm: 0.023; SizeArea_mm2: 4; AEC Category: Q101; IdsMax_A: 5A; SizeAreaWB_mm2: 9; U/M: EA
R89-R104 = CMP-0022109-5: RES, 1.00 k, 1%, 0.1 W, AEC-Q200 Grade 0, 0603; Manufacturer: Vishay-Dale; Power_W: 100mW; TempCo: 100 ppm/C; Value_Code: 1k00; Value: 1.00k; EIA_Code: E96; Res_ohm: 1k; SizeX_mm: 1.6; SizeY_mm: 0.8; SizeZ_mm: 1; Value2: 0.1W; SizeArea_mm2: 1.28; AEC Qualified: Y; VDC_V: 75V; AEC Category: Q200; AEC Grade: 0
R105-R120 R444 = CMP-0021990-4: as R81 on sheet 14_XDS110_Debugger
R121 R122 = CMP-0022902-5: as R79 on sheet 14_XDS110_Debugger
R123 R124 = CMP-0023341-3: as R87 on sheet 14_XDS110_Debugger
R443 R447 = CMP-0025874-4: RES, 0, 5%, 0.1 W, AEC-Q200 Grade 0, 0603; Manufacturer: Panasonic; Power_W: 100mW; TempCo: 600 ppm/C; Value_Code: 0000; Value: 0; EIA_Code: E24; SizeX_mm: 1.6; SizeY_mm: 0.8; SizeZ_mm: 1; Value2: 0.1W; SizeArea_mm2: 1.28; AEC Qualified: Y; VDC_V: 50V; AEC Category: Q200; SizeAreaWB_mm2: 4.68
R445 R446 = CMP-0080084-1: RES, 10.0 k, 0.1%, 0.1 W, AEC-Q200 Grade 0, 1.6x0.8mm; Manufacturer: Panasonic; Value_Code: 10k0; SizeAreaWB_mm2: 4.68; SizeArea_mm2: 1.28; AEC Qualified: Y; AEC Category: Q200; Res_ohm: 10k; Value: 10.0k; SizeZ_mm: 0.55; TempCo: 10 ppm/C; AEC Grade: 0; Power_W: 100mW; VDC_V: 150V; SizeY_mm: 0.8; Value2: 0.1W; SizeX_mm: 1.6
S1 S2 = CMP-0002229-1: Switch, SPST, 8 Pos, 25mA, 24VDC, SMD; Manufacturer: CTS Electrocomponents; CurrentRating_mA: 25A; PositionCount: 8; VDC_V: 24V; SwitchFunction: Off-On
U17 = CMP-0035022-1: Arm® Cortex®-R5F-based MCU with industrial communications and security up to 800 MHz 293-FCCSP -40 to 125; Manufacturer: Texas Instruments; Number Of Pwm Channels: 7; Number Of Usb Channels: 1; Number Of Cores: 2; Standoff Height: 0.15mm; Ram Size: 2MBytes; Number Of I2C Channels: 3; Number Of Spi Channels: 4; SizeZ_mm: 1mm; Frequency_Fixed: 800MHz; Number Of I/Os: 148; AEC Qualified: No; Data Bus Width: 32bits; Core Architecture: Arm Cortex-R5F, Arm Cortex-M4F; TJmax_C: +125°C; Number Of Timers/Counters: 16; Max Supply Voltage: 3.465V; Min Supply Voltage: 810mV; Interface: I2C,SPI,UART,CAN,USB,Ethernet,PCIe,Other; Number Of Adc Channels: 8; Memory Type: OTHER
U33 = CMP-0097670-1: FLASH - NOR Memory IC 512Mbit SPI - Quad I/O 166 MHz 16-SOIC; Manufacturer: Infineon; Access Time: 6.5ns; AEC Qualified: No; Frequency_Fixed: 166MHz; Max Supply Voltage: 3.6V; Memory Type: FLASH,NOR; Min Supply Voltage: 2.7V; Nominal Supply Current: 10-53mA; SizeZ_mm: 2.65mm; Standoff Height: 0.1mm; TaMax_C: +85°C; TaMin_C: -40°C
U34 = CMP-0051588-2: Single 2-Input Positive-AND Gate, DBV0005A, LARGE T&R; Manufacturer: Texas Instruments; Logic: True; ICC @ Nom Voltage(Max)(mA): 0.01; VCC(Min)(V): 1.65; Bits(#): 1; Rating: Catalog; Schmitt Trigger: No; Voltage(Nom)(V): 1.8,2.5,3.3,5; Output Drive (IOL/IOH)(Max)(mA): 32/-32; Gate Type: AND; tpd @ Nom Voltage(Max)(ns): 4.5,6,4,5; VCC(Max)(V): 5.5; Output Type: CMOS; F @ Nom Voltage(Max)(Mhz): 150; Input Type: CMOS/TTL; Technology Family: LVC; AEC Category: Q200; AEC Qualified: N; CompType: IC

## Sheet 16_AM243x_Reset.SchDoc
size 431 x 279 mm; Date: Not shown in title block; ApprovedBy: Not shown in title block; CheckedBy: Not shown in title block; Author: Not shown in title block; CompanyName: Not shown in title block; Engineer: Not shown in title block; Organization: Not shown in title block; Address1: Not shown in title block; Address2: Not shown in title block; Address3: Not shown in title block; Address4: Not shown in title block; DocumentNumber: 8; Revision: Use project parameter SCH_Rev; SheetNumber: 8; SheetTotal: 18; PageSetup: Record=PageOptions¦CenterHorizontal=True¦CenterVertical=True¦PrintScale=1.00¦XCorrection=1.00¦YCorrection=1.00¦PrintKind=0¦BorderSize=5000000¦LeftOffset=0¦BottomOffset=0¦Orientation=2¦PaperLength=1000¦PaperWidth=1000¦Scale=100¦PaperSource=15¦PrintQuality=600¦MediaType=1¦DitherType=10¦PaperKind=Letter¦PrintScaleMode=1
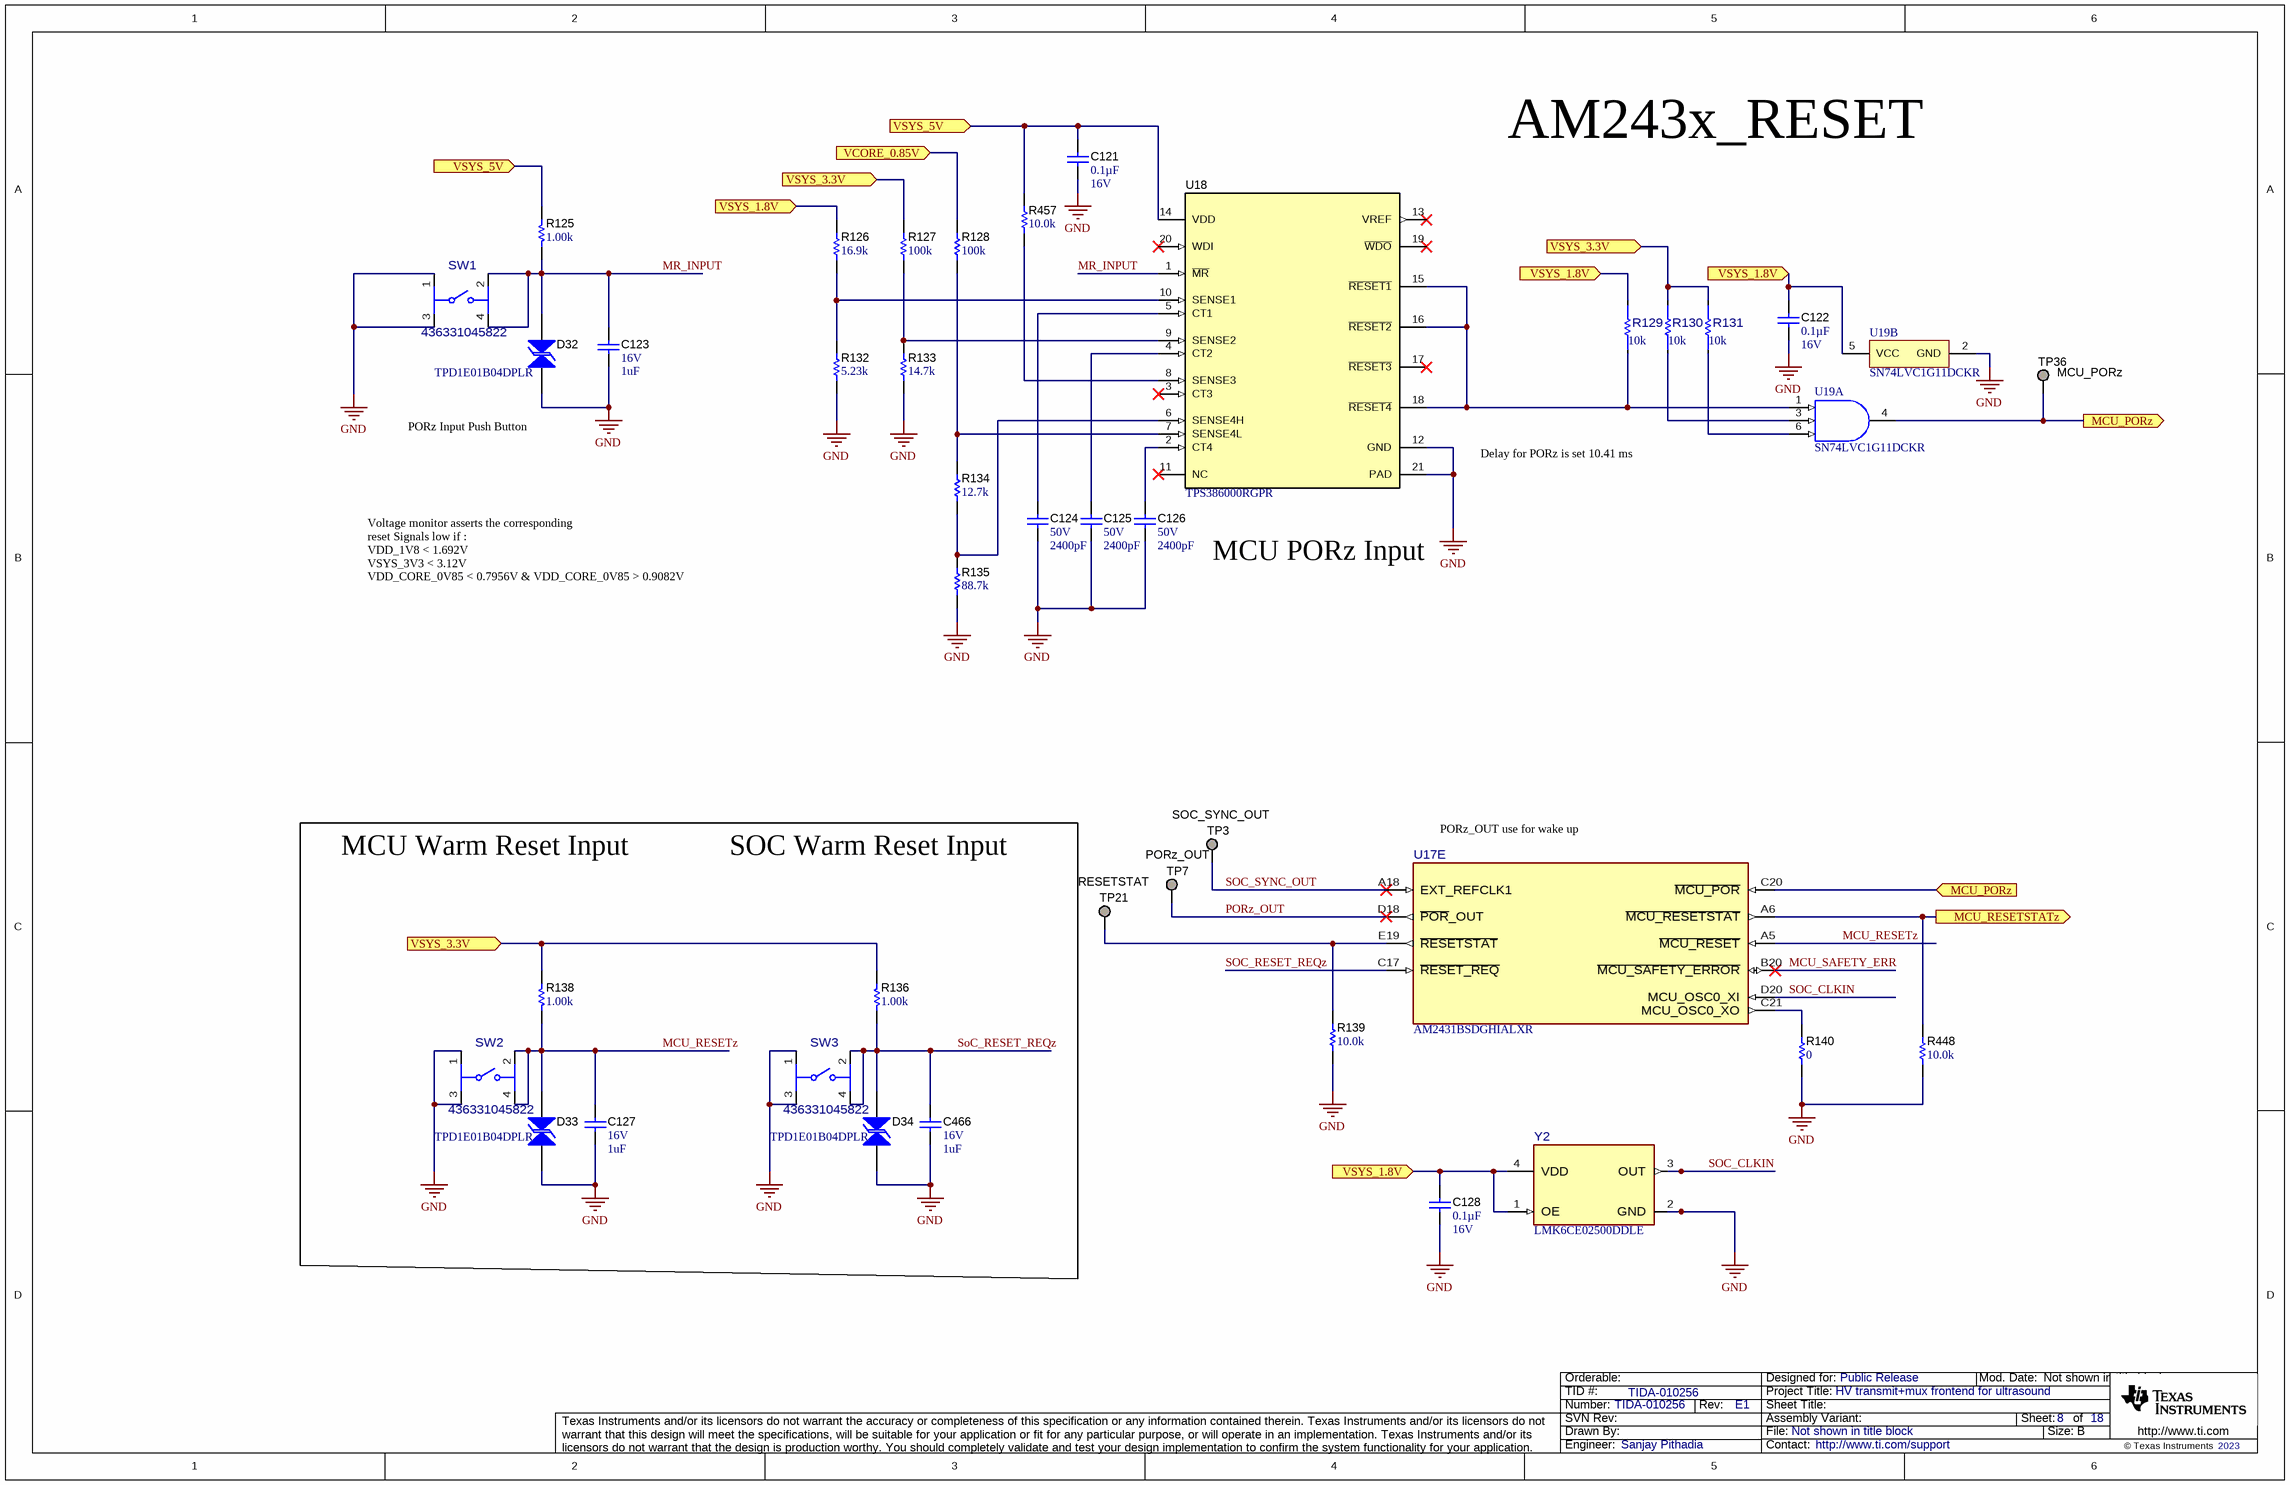
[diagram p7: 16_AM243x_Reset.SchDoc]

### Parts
C121  ValueDisplayed: 0.1µF  VDC_V: 16V  [0201_033]  (hidden comment: GRM033R61C104KE14D)
C122  ValueDisplayed: 0.1µF  VDC_V: 16V  [0201_033]  (hidden comment: GRM033R61C104KE14D)
C123  VDC_V: 16V  ValueDisplayed: 1uF  [0603]  (hidden comment: C0603C105K4PACTU)
C124  VDC_V: 50V  ValueDisplayed: 2400pF  [0603]  (hidden comment: GRM1885C1H242JA01D)
C125  VDC_V: 50V  ValueDisplayed: 2400pF  [0603]  (hidden comment: GRM1885C1H242JA01D)
C126  VDC_V: 50V  ValueDisplayed: 2400pF  [0603]  (hidden comment: GRM1885C1H242JA01D)
C127  VDC_V: 16V  ValueDisplayed: 1uF  [0603]  (hidden comment: C0603C105K4PACTU)
C128  ValueDisplayed: 0.1µF  VDC_V: 16V  [0201_033]  (hidden comment: GRM033R61C104KE14D)
C466  VDC_V: 16V  ValueDisplayed: 1uF  [0603]  (hidden comment: C0603C105K4PACTU)
D32  TPD1E01B04DPLR  [DPL0002A]
D33  TPD1E01B04DPLR  [DPL0002A]
D34  TPD1E01B04DPLR  [DPL0002A]
R125  ValueDisplayed: 1.00k  [0603]  (hidden comment: ERA3AEB102V)
R126  ValueDisplayed: 16.9k  [0402]  (hidden comment: CRCW040216K2FKED)
R127  ValueDisplayed: 100k  [0402]  (hidden comment: CRCW040216K2FKED)
R128  ValueDisplayed: 100k  [0402]  (hidden comment: CRCW040216K2FKED)
R129  value 10k  [FP-RC0402JR-0710KL_0402-MFG]  (hidden comment: RC0402JR-0710KL)
R130  value 10k  [FP-RC0402JR-0710KL_0402-MFG]  (hidden comment: RC0402JR-0710KL)
R131  value 10k  [FP-RC0402JR-0710KL_0402-MFG]  (hidden comment: RC0402JR-0710KL)
R132  ValueDisplayed: 5.23k  [0402]  (hidden comment: CRCW040216K2FKED)
R133  ValueDisplayed: 14.7k  [0402]  (hidden comment: CRCW040216K2FKED)
R134  ValueDisplayed: 12.7k  [0402]  (hidden comment: CRCW040216K2FKED)
R135  ValueDisplayed: 88.7k  [0402]  (hidden comment: CRCW040216K2FKED)
R136  ValueDisplayed: 1.00k  [0603]  (hidden comment: ERA3AEB102V)
R138  ValueDisplayed: 1.00k  [0603]  (hidden comment: ERA3AEB102V)
R139  ValueDisplayed: 10.0k  [0402]  (hidden comment: PCF0402-12-10KBT1)
R140  ValueDisplayed: 0  [0402]  (hidden comment: RK73Z1ETTP)
R448  ValueDisplayed: 10.0k  [ERA3A]  (hidden comment: ERA3ARB103V)
R457  ValueDisplayed: 10.0k  [0603]  (hidden comment: RT0603DRE0710KL)
SW1  436331045822  [FP-436331045822_SW_TACT-MFG]
SW2  436331045822  [FP-436331045822_SW_TACT-MFG]
SW3  436331045822  [FP-436331045822_SW_TACT-MFG]
TP3  SOC_SYNC_OUT  [TP_SM_1MM]  (no BOM)
TP7  PORz_OUT  [TP_SM_1MM]  (no BOM)
TP21  RESETSTAT  [TP_SM_1MM]  (no BOM)
TP36  MCU_PORz  [TP_SM_1MM]  (no BOM)
U17  AM2431BSDGHIALXR  [ALX0293A-MFG]  (part E of 9)
U18  TPS386000RGPR  [RGP0020A]
U19  SN74LVC1G11DCKR  [DCK0006A_N]  (parts A,B of 2)
Y2  LMK6CE02500DDLE  [DLE0004A-MFG]

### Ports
MCU_PORz (in), MCU_PORz (out), MCU_RESETSTATz (out), VCORE_0.85V (in), VSYS_1.8V (in), VSYS_3.3V (in), VSYS_5V (in)

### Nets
GND: C121.2 C122.2 C123.2 C124.2 C125.2 C126.2 C127.2 C128.2 C466.2 D32.1 D33.1 D34.1 R132.1 R133.1 R135.1 R139.1 R140.1 R448.1 SW1.1 SW1.3 SW2.1 SW2.3 SW3.1 SW3.3 U18.12(GND) U18.21(PAD) U19.2(GND) Y2.2(GND)
MCU_RESETz: C127.1 D33.2 R138.2 SW2.2 SW2.4 U17.A5(~{MCU_RESET})
MCU_SAFETY_ERR: U17.B20(~{MCU_SAFETY_ERROR})
MR_INPUT: C123.1 D32.2 R125.2 SW1.2 SW1.4 U18.1(~{MR})
PORz_OUT: TP7.1 U17.D18(~{POR}_OUT)
SOC_CLKIN: U17.D20(MCU_OSC0_XI) Y2.3(OUT)
SOC_RESET_REQz: C466.1 D34.2 R136.2 SW3.2 SW3.4 U17.C17(~{RESET_REQ})
SOC_SYNC_OUT: TP3.1 U17.A18(EXT_REFCLK1)
VCORE_0.85V: R128.2 ; port VCORE_0.85V
VSYS_1.8V: C122.1 C128.1 R126.2 R129.2 U19.5(VCC) Y2.1(OE) Y2.4(VDD) ; port VSYS_1.8V
VSYS_3.3V: R127.2 R130.2 R131.2 R136.1 R138.1 ; port VSYS_3.3V
VSYS_5V: C121.1 R125.1 R457.2 U18.14(VDD) ; port VSYS_5V
NetC124_1: C124.1 U18.5(CT1)
NetC125_1: C125.1 U18.4(CT2)
NetC126_1: C126.1 U18.2(CT4)
NetR126_1: R126.1 R132.2 U18.10(SENSE1)
NetR127_1: R127.1 R133.2 U18.9(SENSE2)
NetR128_1: R128.1 R134.2 U18.7(SENSE4L)
NetR129_1: R129.1 U18.15(~{RESET1}) U18.16(~{RESET2}) U18.18(~{RESET4}) U19.1(A)
NetR130_1: R130.1 U19.3(B)
NetR131_1: R131.1 U19.6(C)
NetR134_1: R134.1 R135.2 U18.6(SENSE4H)
NetR139_2: R139.2 TP21.1 U17.E19(~{RESETSTAT})
NetR140_2: R140.2 U17.C21(MCU_OSC0_XO)
NetR447_1: R448.2 U17.A6(~{MCU_RESETSTAT}) ; port MCU_RESETSTATz
NetR457_1: R457.1 U18.8(SENSE3)
NetTP36_1: TP36.1 U17.C20(~{MCU_POR}) U19.4(Y) ; port MCU_PORz

Not connected (* = marked no-connect by the designer): U18 3(CT3)* 11(NC)* 13(VREF)* 17(~{RESET3})* 19(~{WDO})* 20(WDI)*

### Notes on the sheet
- AM243x_RESET
- (near D32) PORz Input Push Button
- Delay for PORz is set 10.41 ms
- MCU PORz Input
- Voltage monitor asserts the corresponding
  reset Signals low if :
  VDD_1V8 < 1.692V
  VSYS_3V3 < 3.12V
  VDD_CORE_0V85 < 0.7956V & VDD_CORE_0V85 > 0.9082V
- PORz_OUT use for wake up other parts
- MCU Warm Reset Input
- SOC Warm Reset Input

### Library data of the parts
C121 C122 C128 = CMP-0086192-1: as C461 on sheet 15_AM243x_BootMode
C123 C127 C466 = CMP-0006868-5: CAP, CERM, 1 uF, 16 V, +/- 10%, X5R, 0603; Manufacturer: Kemet; TaMin_C: -55°C; Polarized: N; SizeAreaWB_mm2: 4.68; Value1: Unknown; U/M: EA; Value: 1uF; TaMax_C: 85°C; SizeZ_mm: 1; SizeX_mm: 1.6; SizeY_mm: 0.8; SizeArea_mm2: 1.28; Cap_F: 1µF; AEC Category: Q200
C124-C126 = CMP-0007201-4: CAP, CERM, 2400 pF, 50 V, +/- 5%, C0G/NP0, 0603; Manufacturer: MuRata; TaMin_C: -55°C; Polarized: N; SizeAreaWB_mm2: 4.68; Value1: Unknown; U/M: EA; Value: 2400pF; TaMax_C: 125°C; SizeZ_mm: 1; SizeX_mm: 1.6; SizeY_mm: 0.8; SizeArea_mm2: 1.28; Cap_F: 2.4nF; AEC Category: Q200
D32-D34 = CMP-0073601-1: 1-Channel ESD Protection Diode for USB Type-C and Thunderbolt 3, DPL0002A (X2SON-2); Alternate PartNumber: TPD1E01B04DPLT; Alternate Manufacturer: Texas Instruments; SizeAreaWB_mm2: 2.08; U/M: EA; SizeZ_mm: 0.32; SizeX_mm: 0.6; SizeY_mm: 0.3; SizeArea_mm2: 0.18; CompType: IC
R125 R136 R138 = CMP-0078581-1: RES, 1.00 k, 0.1%, 0.1 W, AEC-Q200 Grade 0, 0603; Manufacturer: Panasonic; Power_W: 100mW; TempCo: 25 ppm/C; Value_Code: 1k00; Value: 1.00k; EIA_Code: E192; Res_ohm: 1k; SizeX_mm: 1.6; SizeY_mm: 0.8; SizeZ_mm: 1; Value2: 0.1W; SizeArea_mm2: 1.28; AEC Qualified: Y; AEC Grade: 0; AEC Category: Q200
R126 = CMP-0026040-3: RES, 16.9k, 1%, 0.063 W, AEC-Q200 Grade 0, 0402; Manufacturer: Vishay-Dale; Power_W: 63mW; TempCo: 100 ppm/C; Value_Code: 16k2; Value: 16.2k; EIA_Code: E96; SizeX_mm: 1; SizeY_mm: 0.5; SizeZ_mm: 0.6; Value2: 0.063W; AEC Qualified: Y; VDC_V: 50V; AEC Category: Q200; AEC Grade: 0
R127 R128 = CMP-0026040-3: RES, 100k, 1%, 0.063 W, AEC-Q200 Grade 0, 0402; Manufacturer: Vishay-Dale; Power_W: 63mW; TempCo: 100 ppm/C; Value_Code: 16k2; Value: 16.2k; EIA_Code: E96; SizeX_mm: 1; SizeY_mm: 0.5; SizeZ_mm: 0.6; Value2: 0.063W; AEC Qualified: Y; VDC_V: 50V; AEC Category: Q200; AEC Grade: 0
R129-R131 = CMP-0094798-1: Res Thick Film 0402 10K Ohm 5% 0.063W(1/16W) ±100ppm/C Pad SMD T/R; Manufacturer: YAGEO; AEC Qualified: No; Category Cd01000Bfc2916C6: Single Components; SizeZ_mm: 0.4mm; VDC_V: 50V; Category 5C6A91606D4187Ad: Resistors; TempCo: 100ppm/°C; Power_W: 63mW; Category 7542B8484461Ae85: Passive Components
R132 = CMP-0026040-3: RES, 5.23k, 1%, 0.063 W, AEC-Q200 Grade 0, 0402; Manufacturer: Vishay-Dale; Power_W: 63mW; TempCo: 100 ppm/C; Value_Code: 16k2; Value: 16.2k; EIA_Code: E96; SizeX_mm: 1; SizeY_mm: 0.5; SizeZ_mm: 0.6; Value2: 0.063W; AEC Qualified: Y; VDC_V: 50V; AEC Category: Q200; AEC Grade: 0
R133 = CMP-0026040-3: RES, 14.7k, 1%, 0.063 W, AEC-Q200 Grade 0, 0402; Manufacturer: Vishay-Dale; Power_W: 63mW; TempCo: 100 ppm/C; Value_Code: 16k2; Value: 16.2k; EIA_Code: E96; SizeX_mm: 1; SizeY_mm: 0.5; SizeZ_mm: 0.6; Value2: 0.063W; AEC Qualified: Y; VDC_V: 50V; AEC Category: Q200; AEC Grade: 0
R134 = CMP-0026040-3: RES, 12.7k, 1%, 0.063 W, AEC-Q200 Grade 0, 0402; Manufacturer: Vishay-Dale; Power_W: 63mW; TempCo: 100 ppm/C; Value_Code: 16k2; Value: 16.2k; EIA_Code: E96; SizeX_mm: 1; SizeY_mm: 0.5; SizeZ_mm: 0.6; Value2: 0.063W; AEC Qualified: Y; VDC_V: 50V; AEC Category: Q200; AEC Grade: 0
R135 = CMP-0026040-3: RES, 88.7k, 1%, 0.063 W, AEC-Q200 Grade 0, 0402; Manufacturer: Vishay-Dale; Power_W: 63mW; TempCo: 100 ppm/C; Value_Code: 16k2; Value: 16.2k; EIA_Code: E96; SizeX_mm: 1; SizeY_mm: 0.5; SizeZ_mm: 0.6; Value2: 0.063W; AEC Qualified: Y; VDC_V: 50V; AEC Category: Q200; AEC Grade: 0
R139 = CMP-0026797-1: RES, 10.0 k, 0.1%, 0.063 W, 0402; Manufacturer: TT Electronics/IRC; Power_W: 63mW; TempCo: 10 ppm/C; Value_Code: 10k0; U/M: EA; Value: 10.0k; EIA_Code: E192; Res_ohm: 10k; SizeX_mm: 1; SizeY_mm: 0.5; SizeZ_mm: 0.6; Value2: 0.063W; VDC_V: 25V; AEC Category: Q200
R140 = CMP-0027007-2: RES, 0, 5%, 0.063 W, AEC-Q200 Grade 0, 0402; Manufacturer: KOA Speer; Power_W: 63mW; TempCo: ppm/C; Value_Code: 0000; U/M: EA; Value: 0; EIA_Code: E24; SizeX_mm: 1; SizeY_mm: 0.5; SizeZ_mm: 0.6; Value2: 0.063W; AEC Qualified: Y; AEC Category: Q200
R448 = CMP-0080084-1: as R445 on sheet 15_AM243x_BootMode
R457 = CMP-0024586-3: RES, 10.0 k, 0.5%, 0.1 W, 0603; Manufacturer: Yageo America; Power_W: 100mW; TempCo: 50 ppm/C; Value_Code: 10k0; U/M: EA; Value: 10.0k; EIA_Code: E192; Res_ohm: 10k; SizeX_mm: 1.6; SizeY_mm: 0.8; SizeZ_mm: 1; Value2: 0.1W; SizeArea_mm2: 1.28; VDC_V: 75V; AEC Category: Q200
SW1-SW3 = CMP-0092977-1: Tactile Switch SPST-NO Side Actuated Surface Mount, Right Angle; Manufacturer: Wurth; Operating Force: 220gf; Coil Resistance_ohm: 100mΩ; SizeZ_mm: 1.65mm; Electromechanical Life: 100000Cycles; AEC Qualified: No; Contact Current Rating: 50mA; VDC_V: 12V
TP3 TP7 TP21 TP36 = CMP-0003825-1: 1mm Test Point, SMT; Manufacturer: Any
U17 = CMP-0035022-1: as U17 on sheet 15_AM243x_BootMode
U18 = CMP-0079268-1: Quad Supply Voltage Supervisors with Programmable Delay and Watchdog Timer, RGP0020A (VQFN-20); Manufacturer: Texas Instruments; Alternate PartNumber: TPS386000RGPT; SizeAreaWB_mm2: 25; SizeArea_mm2: 16; AEC Qualified: N; AEC Category: Q200; SizeZ_mm: 1; Green_REACh: Passed; SizeY_mm: 4; Green_Lifecycle: Active; CompType: IC
U19 = CMP-0051216-3: Single 3-Input Positive-AND Gate, DCK0006A (SOT-SC70-6); Manufacturer: Texas Instruments; Output Type: CMOS; Bits(#): 1; Input Type: CMOS/TTL; Technology Family: LVC; Schmitt Trigger: No; VCC(Max)(V): 5.5; Gate Type: AND; Rating: Catalog; Output Drive (IOL/IOH)(Max)(mA): 32/-32; ICC @ Nom Voltage(Max)(mA): 0.01; VCC(Min)(V): 1.65; F @ Nom Voltage(Max)(Mhz): 150; Logic: True; Voltage(Nom)(V): 1.8,2.5,3.3,5; tpd @ Nom Voltage(Max)(ns): 20,7.8,6.2,4.6; AEC Category: Q200; AEC Qualified: N; CompType: IC; SizeAreaWB_mm2: 9.3; SizeArea_mm2: 4.2; SizeX_mm: 2.1; SizeY_mm: 2.0; SizeZ_mm: 1.1
Y2 = CMP-0096252-1: High-Performance BAW Oscillator, LVCMOS; <1ps, +/- 50ppm; 1.8V, -40C to 105C and DLE package; Manufacturer: Texas Instruments; Max Supply Voltage: 1.89V; Min Supply Voltage: 1.71V; TaMax_C: +105°C; Frequency_Fixed: 25MHz; AEC Qualified: No; Load Capacitance: 30pF; Standoff Height: 0mm; SizeZ_mm: 1mm; TJmax_C: +125°C; TaMin_C: -40°C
